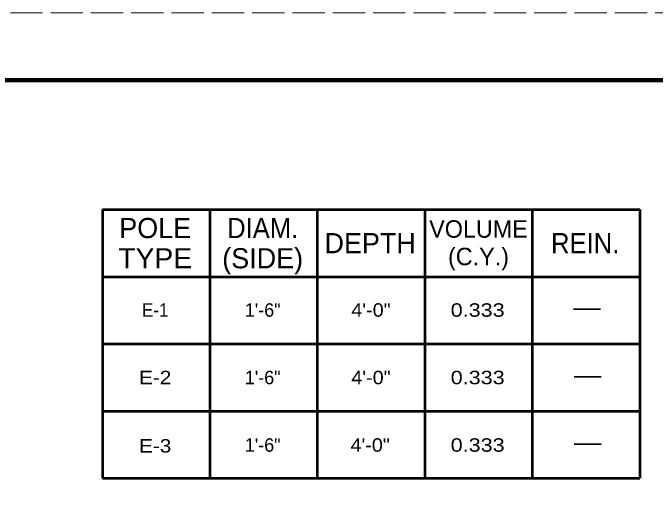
# Model space of a CAD drawing. Extents: x -608 to 72, y 36 to 476.
# Drawn here: x -301.5 to -205.8, y 403.3 to 475.6 of the extents above; entities that cross this region are included whole.
import ezdxf
from ezdxf.enums import TextEntityAlignment as Align

# ---------------------------------------------------------------- set-up
doc = ezdxf.new("R2010")
doc.units = 0
doc.header["$LTSCALE"] = 0.8
doc.linetypes.add('LONG_DASHED', pattern=[7.5, 6, -1.5])
doc.layers.add('1', color=7, linetype='Continuous', lineweight=53)
doc.layers.add('61', color=7, linetype='Continuous', lineweight=35)

msp = doc.modelspace()

# ---------------------------------------------------------------- linework, layer by layer
at = {"layer": '1'}
for p, q in [((-272.1291, 446.3044), (-272.1291, 406.3044)), ((-256.1291, 446.3044), (-256.1291, 406.3044)), ((-240.1291, 446.3044), (-240.1291, 406.3044)), ((-224.1291, 446.3044), (-224.1291, 406.3044)), ((-208.1291, 446.3044), (-208.1291, 406.3044)), ((-288.1291, 436.3044), (-208.1291, 436.3044)), ((-288.1291, 426.3044), (-208.1291, 426.3044)), ((-288.1291, 416.3044), (-208.1291, 416.3044)), ((-288.1291, 406.3044), (-208.1291, 406.3044))]:
    msp.add_line(p, q, dxfattribs=at)
at = {"layer": '1', "lineweight": 35}
for p, q in [((-217.9862, 431.4755), (-213.9862, 431.4755)), ((-217.8621, 421.4266), (-213.8621, 421.4266)), ((-217.8621, 411.3777), (-213.8621, 411.3777))]:
    msp.add_line(p, q, dxfattribs=at)
at = {"layer": '1'}
for points in [[(-288.1291, 446.3044), (-272.1291, 446.3044), (-256.1291, 446.3044), (-240.1291, 446.3044), (-224.1291, 446.3044), (-208.1291, 446.3044)], [(-288.1291, 446.3044), (-288.1291, 436.3044), (-288.1291, 426.3044), (-288.1291, 416.3044), (-288.1291, 406.3044)]]:
    msp.add_lwpolyline(points, dxfattribs=at)
at = {"layer": '61', "linetype": 'LONG_DASHED', "lineweight": 13}
msp.add_line((-607.8231, 475.5947), (72.1969, 475.5947), dxfattribs=at)
at = {"layer": '61', "lineweight": 158}
msp.add_lwpolyline([(61.2169, 465.5947), (-577.8231, 465.5947), (-577.8231, 45.5747)], dxfattribs=at)

# ---------------------------------------------------------------- texts
at = {"layer": '1'}
for s, height, p in [('POLE', 3, (-280.2646, 442.0567)), ('VOLUME', 2.6, (-232.1291, 442.1187)), ('DEPTH', 3, (-248.257, 439.8067)), ('(SIDE)', 3, (-264.2608, 437.5567)), ('(C.Y.)', 2.6, (-232.129, 438.0188)), ('1\'-6"', 2, (-264.2608, 430.3513)), ('1\'-6"', 2, (-264.2608, 420.3024)), ('1\'-6"', 2, (-264.2608, 410.2535))]:
    msp.add_text(s, height=height, dxfattribs=at).set_placement(p, align=Align.CENTER)
for s, height, width, p in [('DIAM.', 3, 0.95, (-264.2608, 442.0567)), ('REIN.', 3, 0.95, (-216.2493, 439.8067)), ('TYPE', 3, 1.05, (-280.2646, 437.5567)), ('E-1', 2, 0.95, (-280.2647, 430.3513)), ('4\'-0"', 2, 1.1, (-248.1329, 430.3513)), ('0.333', 2, 1.2, (-232.2532, 430.3513)), ('E-2', 2, 1.15, (-280.2646, 420.3024)), ('4\'-0"', 2, 1.1, (-248.1329, 420.3024)), ('0.333', 2, 1.2, (-232.2532, 420.3024)), ('E-3', 2, 1.15, (-280.2646, 410.1295)), ('4\'-0"', 2, 1.1, (-248.257, 410.2535)), ('0.333', 2, 1.2, (-232.2532, 410.2535))]:
    msp.add_text(s, height=height, dxfattribs=dict(at, width=width)).set_placement(p, align=Align.CENTER)

doc.saveas('drawing.dxf')
